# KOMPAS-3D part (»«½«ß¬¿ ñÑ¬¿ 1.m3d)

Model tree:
1. Эскиз:1
2. Операция выдавливания:1
     Толщина стенки 1 = 2.3; Толщина стенки 2 = 2.3; Расстояние 1 = 0.6; Расстояние 2 = 0.6
3. Эскиз:2
4. Операция выдавливания:2
     Толщина стенки 1 = 2.3; Толщина стенки 2 = 2.3; Расстояние 1 = 0.6; Расстояние 2 = 0.6
5. Эскиз:3
6. Вырезать элемент выдавливания:1
     Толщина стенки 1 = 3; Толщина стенки 2 = 3; Расстояние 1 = 10
7. Эскиз:4
8. Вырезать элемент выдавливания:2
     Толщина стенки 1 = 3; Толщина стенки 2 = 3; Расстояние 1 = 10
9. Вырезать элемент выдавливания:3
     Расстояние 1 = 10
